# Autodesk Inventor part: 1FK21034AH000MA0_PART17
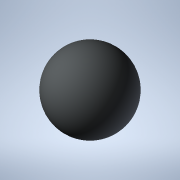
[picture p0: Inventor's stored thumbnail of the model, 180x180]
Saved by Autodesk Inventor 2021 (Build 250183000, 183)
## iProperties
Created: 2025-04
Part Number: 1FK21034AH000MA0_PART17
Material: Generic
Catalog Web Link: www.3dfindit.com
Description: -Servo synchronous motor
Document SubType Name: Modeling
Designer: psAdmin
Mass: 0.113097 g
Surface Area: 1.13097 cm^2
Volume: 0.113097 cm^3
Density: 1 g/cm^3
Appearance: PSOLRGB-212-217-219
Category: PARTsolutions
Title: 1FK21034AH000MA0_PART17
Author: Cadenas PARTsolutions
Comments: Servo synchronous motor
Sending System: PARTsolutions
Preprocessor: ST-DEVELOPER v19.3
PSOL_IDENT_0: {$CADENAS_DATA/23d-libs/siemens_ag/_cat_/ec/b7/1fk21034ah000ma0.prj},216 {VTYP=3D},{NB=1FK21034AH000
PSOL_IDENT_1: MA0_PART17},{LINA=1FK21034AH000MA0_PART17},{NN=1FK21034AH000MA0_PART17},{NOPRJ=TRUE},{DATE=19.08.202
PSOL_IDENT_2: 5 14:01:05},{GEOMDATE=30.07.2025 02:01:02},{VERSION=},{LINEID=10},{WBVAR=},{WBNUMERIC=}  {NB=1FK2103
PSOL_IDENT_3: 4AH000MA0_PART17},{LINA=1FK21034AH000MA0_PART17},{KT=DUMMY},{PREVIEW=../../../_pool_/7c/50/p_d211_xx
PSOL_IDENT_4: _00932j.png},{DESCSHORT=SIMOTICS S-1FK2 HD, SINAMICS S210 3AC 400V-480V, 1.01 Nm, 4500 rpm},{DESCLON
PSOL_IDENT_5: G=SIMOTICS S-1FK2 HD servo motor M0=1.27 Nm; PN = 0.48 kW at nN=4500 rpm (380-480 V); PN = 0.3 kW at
PSOL_IDENT_6: nN=2500 rpm (200-240 V); degree of protection IP64; cylindrical shaft D14 x 30 mm; absolute encoder
PSOL_IDENT_7: 22-bit + 12-bit multiturn (encoder AM22DQC); with OCC interface; plug size M17, rotatable; SIMOTICS
PSOL_IDENT_8: S-1FK2 servomotorfor a wide range of uses in industrial environments. SIMOTICS S‑1FK2 servomotors a
PSOL_IDENT_9: re compact synchronous motors with a high dynamic performance that set themselves apart as a result
PSOL_IDENT_10: of their high power density, degree of protection and overload capability. The motors are available
PSOL_IDENT_11: in two variants: as High Dynamic variant (highest dynamic performance as a result of the low intrins
PSOL_IDENT_12: ic moment of inertia for applications demanding a high dynamic performance with low moved masses) -
PSOL_IDENT_13: and as Compact variant (precise and stable closed-loop control for medium up to large moved masses a
PSOL_IDENT_14: s a result of a medium intrinsic moment of inertia). SIMOTICSS‑1FK2 servomotors fully exploit their
PSOL_IDENT_15: strengths in a system with the SINAMICSS210 frequency converter and simple connection using the one
PSOL_IDENT_16: cable connection (OCC). Advantages include the short control and positioning times, fast and precise
PSOL_IDENT_17: correction of disturbing quantities as well as stable control with a high dynamic performance. The
PSOL_IDENT_18: servo motors can be configured to address a wide range of requirements. For example with and without
PSOL_IDENT_19: holding brake, IP64 or IP65 degree of protection, singleturn or multiturn absolute encoders - to na
PSOL_IDENT_20: me just a few. Further, the servomotors are available in different shaft heights extending from 20 t
PSOL_IDENT_21: o 100. A shaft sealing ring is available to achieve an IP65 degree of protection and for subsequent
PSOL_IDENT_22: mounting at the motor or as spare part. SIMOTICS - the optimum motor for each and every motion contr
PSOL_IDENT_23: ol application.},{INTNO=4034106444822},{SUPPLIERALTNO=1FK2103-4AH00-0MA0},{MANUID=1FK21034AH000MA0},
PSOL_IDENT_24: {MANUNAME=Siemens},{MANUTYPEDESC=SYNCHRONOUS MOTOR 1FK2 HD 1,27 NM},{AAU732=SIMOTICS},{AAO057=S-1FK2
PSOL_IDENT_25: },{AAU734=SIMOTICS S-1FK2 HD servo motor M0=1.27 Nm; PN = 0.48 kW at nN=4500 rpm (380-480 V); PN = 0
PSOL_IDENT_26: .3 kW at nN=2500 rpm (200-240 V); degree of protection IP64; cylindrical shaft D14 x 30 mm; absolute
PSOL_IDENT_27: encoder 22-bit + 12-bit multiturn (encoder AM22DQC); with OCC interface; plug size M17, rotatable;}
PSOL_IDENT_28: ,{AAW338=SYNCHRONOUS MOTOR 1FK2 HD 1,27 NM},{AAO742=SIMOTICS},{AAO663=4034106444822},{NOCUPEROU=1},{
PSOL_IDENT_29: PRICEQUANTITY=1},{QUANTITYMIN=1},{QUANTITYINT=1},{CTN=85015100},{COO=RO},{AAO676=1FK2103-4AH00-0MA0}
PSOL_IDENT_30: ,{AAO677=Siemens AG},{ORDERUNIT=C62},{CONTENTUNIT=C62}
NB: 1FK21034AH000MA0_PART17
NT: Servo synchronous motor
NBSYN: $MANUID._PART17
LINA: 1FK21034AH000MA0_PART17
CATALOG: SIEMENS
PREVIEW: ../../../_pool_/7c/50/p_d211_xx_00932j.png
DESCSHORT: SIMOTICS S-1FK2 HD, SINAMICS S210 3AC 400V-480V, 1.01 Nm, 4500 rpm
DESCLONG: SIMOTICS S-1FK2 HD servo motor M0=1.27 Nm; PN = 0.48 kW at nN=4500 rpm (380-480 V); PN = 0.3 kW at nN=2500 rpm (200-240 V); degree of protection IP64; cylindric
INTNO: 4034106444822
SUPPLIERALTNO: 1FK2103-4AH00-0MA0
MANUID: 1FK21034AH000MA0
MANUNAME: Siemens
MANUTYPEDESC: SYNCHRONOUS MOTOR 1FK2 HD 1,27 NM
AAU732: SIMOTICS
AAO057: S-1FK2
AAU734: SIMOTICS S-1FK2 HD servo motor M0=1.27 Nm; PN = 0.48 kW at nN=4500 rpm (380-480 V); PN = 0.3 kW at nN=2500 rpm (200-240 V); degree of protection IP64; cylindric
AAW338: SYNCHRONOUS MOTOR 1FK2 HD 1,27 NM
AAO742: SIMOTICS
AAO663: 4034106444822.0
NOCUPEROU: 1
PRICEQUANTITY: 1
QUANTITYMIN: 1
QUANTITYINT: 1
CTN: 85015100
COO: RO
ARTICLENO: 1FK21034AH000MA0_PART17
BOMINFO: 1FK21034AH000MA0_PART17
CREATOR: CADENAS GmbH
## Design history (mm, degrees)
feature "2025_04_17_15_01_37_0314"
body "Solid1"
